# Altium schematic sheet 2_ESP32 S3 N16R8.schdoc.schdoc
size 309 x 223 mm; Symbol: Sheet-Symbol_A4; Device: Sheet-Symbol_A4; Company: 嘉立创EDA; Version: V1.0; Page Size: A4; @Project Name: Turbo; @Page Count: 2; @Update Date: 2024-05-26; @Create Date: 2024-02-17; @Schematic Name: Schematic; @Page No: 1; @Page Name: ESP32 S3 N16R8
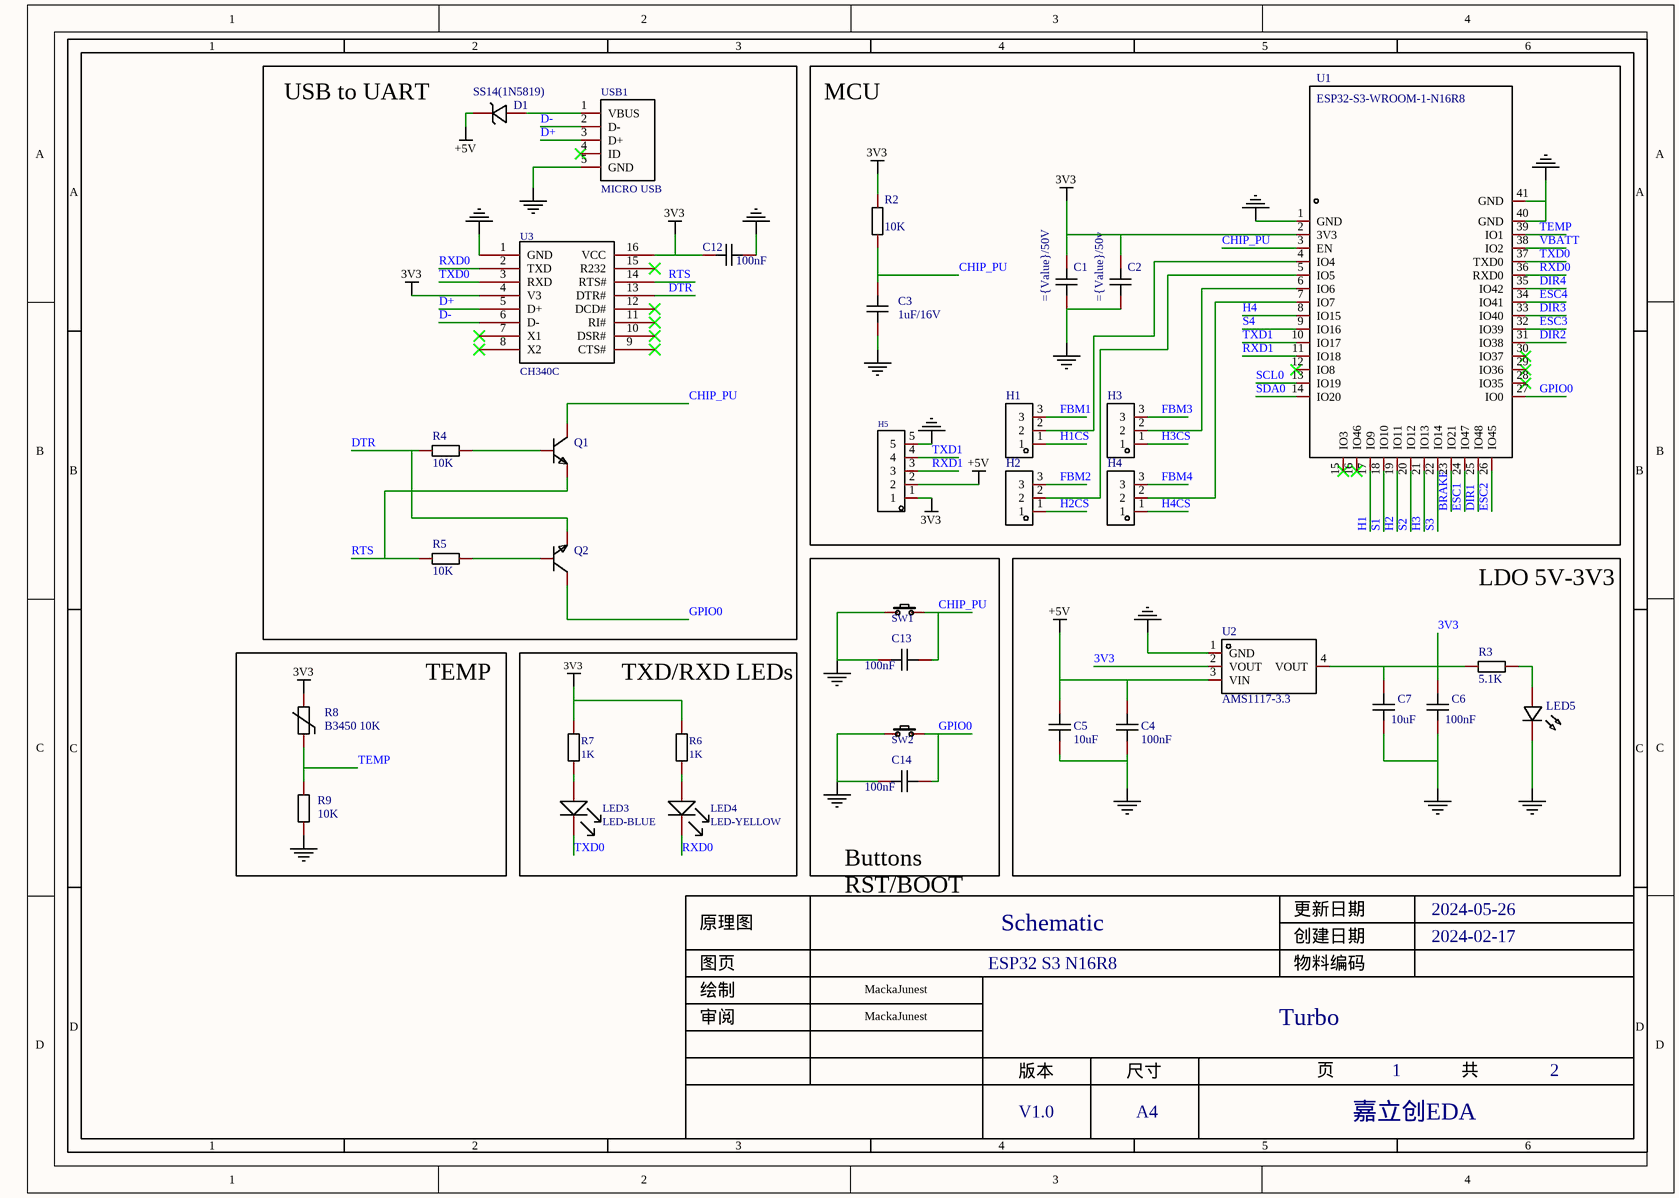
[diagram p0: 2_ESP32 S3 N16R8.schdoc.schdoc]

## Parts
C1  (no value)  [C0603]
C2  (no value)  [C0603]
C3  1uF/16V  [C0603]
C4  100nF  [C0603]
C5  10uF  [C0603]
C6  100nF  [C0603]
C7  10uF  [C0603]
C12  100nF  [C0603]
C13  100nF  [C0603]
C14  100nF  [C0603]
D1  SS14(1N5819)  [SMA_L4.3-W2.7-LS5.1-RD]
H1  HDR-M_2.54_1x3P  [HDR-TH_3P-P2.54-V-M]  (value not drawn)
H2  HDR-M_2.54_1x3P  [HDR-TH_3P-P2.54-V-M]  (value not drawn)
H3  HDR-M_2.54_1x3P  [HDR-TH_3P-P2.54-V-M]  (value not drawn)
H4  HDR-M_2.54_1x3P  [HDR-TH_3P-P2.54-V-M]  (value not drawn)
H5  HDR-M_2.54_1x5P  [HDR-TH_5P-P2.54-V-M]  (value not drawn)
LED3  LED-BLUE  [LED 0805B]
LED4  LED-YELLOW  [LED 0805Y]
LED5  LED_0805-R  [LED_0805]  (value not drawn)
Q1  S8050_SOT_NPN  [S8050_SOT-23]  (value not drawn)
Q2  S8050_SOT_NPN  [S8050_SOT-23]  (value not drawn)
R2  10K  [R0603]
R3  5.1K  [R0603]
R4  10K  [R0603]
R5  10K  [R0603]
R6  1K  [R 0603_L]
R7  1K  [R 0603_L]
R8  B3450 10K  [R0603]
R9  10K  [R0603]
SW1  3x6x5  [TSW SMD-3*6*2.5]  (value not drawn)
SW2  3x6x5  [TSW SMD-3*6*2.5]  (value not drawn)
U1  ESP32-S3-WROOM-1-N16R8  [WIRELM-SMD_ESP32-S3-WROOM-1]
U2  AMS1117-3.3  [SOT-223-3_L6.5-W3.4-P2.30-LS7.0-BR]
U3  CH340C  [SOP16_L]
USB1  MICRO USB  [USB-MICRO_B]

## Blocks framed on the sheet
USB to UART: C12 D1 Q1 Q2 R4 R5 U3 USB1
MCU: C1-C3 H1-H5 R2 U1
LDO 5V-3V3: C4-C7 LED5 R3 U2
TEMP: R8 R9
TXD/RXD LEDs: LED3 LED4 R6 R7

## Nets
3V3: C1.2 C2.2 C6.2 C7.2 C12.1 H5.1 R2.2 R3.1 R6.2 R7.2 R8.2 U1.2(3V3) U2.2(VOUT) U2.4(VOUT) U3.4(V3) U3.16(VCC)
+5V: C4.2 C5.2 D1.1(C) H5.2 U2.3(VIN)
NetC1_1: C1.1 C2.1 C3.1 C4.1 C5.1 C6.1 C7.1 C12.2 C13.1 C14.1 H5.5 LED5.1(C) R9.1 SW1.1 SW2.1 U1.1(GND) U1.40(GND) U1.41(GND) U2.1(GND) U3.1(GND) USB1.5(GND)
BRAKE: U1.23(IO21)
CHIP_PU: C3.2 C13.2 Q1.3 R2.1 SW1.2 U1.3(EN)
D+: U3.5(D+) USB1.3(D+)
D-: U3.6(D-) USB1.2(D-)
DIR1: U1.25(IO48)
DIR2: U1.31(IO38)
DIR3: U1.33(IO40)
DIR4: U1.35(IO42)
DTR: Q2.2 R4.1 U3.13(DTR#)
ESC1: U1.24(IO47)
ESC2: U1.26(IO45)
ESC3: U1.32(IO39)
ESC4: U1.34(IO41)
FBM1: H1.3
FBM2: H2.3
FBM3: H3.3
FBM4: H4.3
GPIO0: C14.2 Q2.3 SW2.2 U1.27(IO0)
H1: U1.17(IO9)
H1CS: H1.1
H2: U1.19(IO11)
H2CS: H2.1
H3: U1.21(IO13)
H3CS: H3.1
H4: U1.8(IO15)
H4CS: H4.1
RTS: Q1.2 R5.1 U3.14(RTS#)
RXD0: LED4.2 U1.36(RXD0) U3.2(TXD)
RXD1: H5.3 U1.11(IO18)
S1: U1.18(IO10)
S2: U1.20(IO12)
S3: U1.22(IO14)
S4: U1.9(IO16)
SCL0: U1.13(IO19)
SDA0: U1.14(IO20)
TEMP: R8.1 R9.2 U1.39(IO1)
TXD0: LED3.2 U1.37(TXD0) U3.3(RXD)
TXD1: H5.4 U1.10(IO17)
VBATT: U1.38(IO2)
NetD1_2: D1.2(A) USB1.1(VBUS)
NetH1_2: H1.2 U1.4(IO4)
NetH2_2: H2.2 U1.5(IO5)
NetH3_2: H3.2 U1.6(IO6)
NetH4_2: H4.2 U1.7(IO7)
NetLED3_1: LED3.1 R7.1
NetLED4_1: LED4.1 R6.1
NetLED5_2: LED5.2(A) R3.2
NetQ1_1: Q1.1 R4.2
NetQ2_1: Q2.1 R5.2

Not connected (* = marked no-connect by the designer): U1 12(IO8)* 15(IO3)* 16(IO46)* 28(IO35)* 29(IO36)* 30(IO37)*; U3 7(X1)* 8(X2)* 9(CTS#)* 10(DSR#)* 11(RI#)* 12(DCD#)* 15(R232)*; USB1 4(ID)*

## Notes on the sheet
- Buttons
  RST/BOOT
- MackaJunest

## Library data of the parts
C1 C2 = CAP_0603: Symbol: CapAcitance; Convert to PCB: yes; Value: 100nF
C3-C7 C12-C14 = CAP_0603: Symbol: CapAcitance; Convert to PCB: yes
D1 = SS14(1N5819)-SMA: Add into BOM: yes
H1-H4 = HDR-M_2.54_1x3P: Symbol: PZ254V-11-03P_C2937625; Convert to PCB: yes
H5 = HDR-M_2.54_1x5P: Manufacturer: MINTRON(明硕); Symbol: MTP125-1105S1; Convert to PCB: yes
LED3 = LED-BLUE: 3DModel: LED0805-RD_EH; Add into BOM: yes
LED4 = LED-YELLOW: 3DModel: LED0805-RD_EH; Add into BOM: yes
LED5 = LED_0805-R: Symbol: LED_R; Convert to PCB: yes
Q1 Q2 = S8050_SOT_NPN: Symbol: NPN; Convert to PCB: yes
R2-R5 R9 = Res_0603: Symbol: 电阻; Convert to PCB: yes
R6 R7 = 1K: BOM名称: 贴片电阻; 3DModel: R0603; Add into BOM: yes
R8 = KNTC0603/10KF3950: Manufacturer: KUU; Add into BOM: yes; Resistance @ 25℃: 10kΩ; B Constant (25℃/50℃): 3950K; Resistance Tolerance: ±1%; B Constant (25℃/85℃): 3987K; Power: 100mW; Steady State Current (Max): 310uA; Description: 阻值(25℃):10kΩ;B值(25℃/50℃):3950K;电阻精度:±1%;功率:100mW;B值精度:±1%;最大稳态电流(25℃):310uA;
SW1 SW2 = 3x6x5: BOM名称: 3x6轻触开关; 3DModel: SW-SMD_TSW-8-16-T40-1; Add into BOM: yes
U1 = ESP32-S3-WROOM-1-N16R8: Manufacturer: ESPRESSIF(乐鑫); Symbol: ESP32-S3-WROOM-1(N16R8); Add into BOM: yes
U2 = AMS1117-3.3_C6186: Manufacturer: AMS; Add into BOM: yes; Output Type: 固定; Output Voltage: 3.3V; MAX Output Current: 1A; Power Supply Rejection Ratio (PSRR): 72dB@(120Hz); Dropout Voltage: 1.3V@(800mA); Output Polarity: 正极; Number of Outputs: 1; Description: 输出类型:固定;最大输入电压:-;输出电压:3.3V;最大输出电流:1A;电源纹波抑制比(PSRR):72dB@(120Hz);输出极性:正极;
U3 = CH340C: 3DModel: SOP-16_L10.0-W3.9-P1.27-LS6.0-TR; Add into BOM: yes
USB1 = MICRO USB: 3DModel: MICRO-USB-SMD_MICRO5.9MMUSB; Add into BOM: yes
